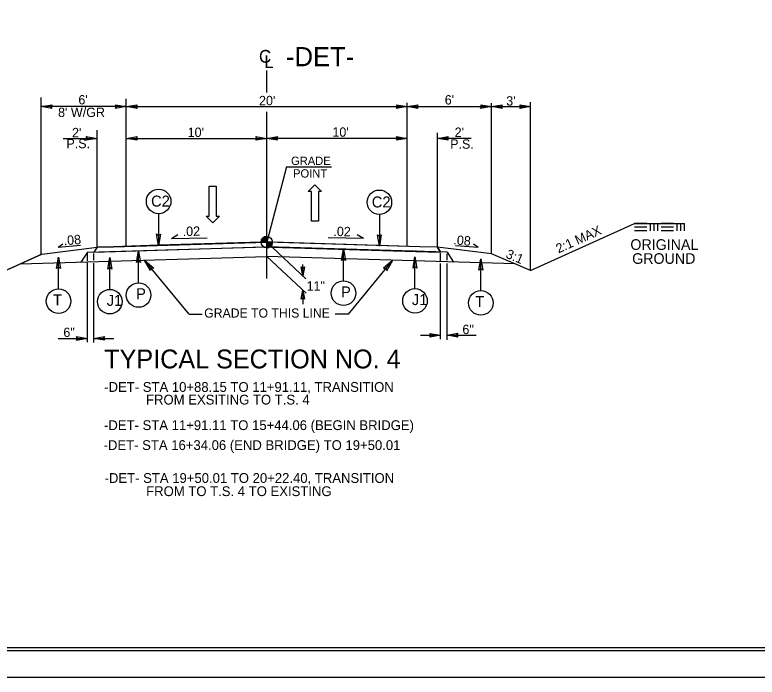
# Model space of a CAD drawing. Extents: x 9470 to 10081, y 10104 to 10463.
# Drawn here: x 9873.4 to 9960.6, y 10104 to 10181.8 of the extents above; entities that cross this region are included whole.
import ezdxf

# ---------------------------------------------------------------- set-up
doc = ezdxf.new("R2010")
doc.units = 0
for name, color, linetype in [('Default', 7, 'Continuous'), ('Old_Level_1', 7, 'Continuous'), ('Old_Level_11', 7, 'Continuous'), ('Old_Level_21', 7, 'Continuous'), ('Old_Level_28', 7, 'Continuous'), ('Old_Level_32', 7, 'Continuous'), ('Prop Dimension', 7, 'Continuous'), ('Prop Lane Arrow CELL', 7, 'Continuous'), ('Sheet Cutting Line CELL', 7, 'Continuous'), ('Sheet Plot Border Inside CELL', 7, 'Continuous'), ('Sheet Plot Border Outside CELL', 7, 'Continuous'), ('Sheet Typical CELL', 7, 'Continuous'), ('Typical Grade Point Symbol CELL', 7, 'Continuous'), ('Typical Hinge Slope Arterial CELL', 7, 'Continuous'), ('Typical ID Circle CELL', 7, 'Continuous'), ('Typical Pavement Slope CELL', 7, 'Continuous'), ('Typical Pavement Slope Information CELL', 7, 'Continuous'), ('Typical Shoulder Slope CELL', 7, 'Continuous'), ('Typical Shoulder Slope Information CELL', 7, 'Continuous'), ('Typical Slope Point Local CELL', 7, 'Continuous'), ('Typical Terminator CELL', 7, 'Continuous'), ('Typical Text General CELL', 7, 'Continuous'), ('Typical Text Grade Point CELL', 7, 'Continuous'), ('Typical Text ID Circle CELL', 7, 'Continuous'), ('Typical Text Label CELL', 7, 'Continuous')]:
    doc.layers.add(name, color=color, linetype=linetype)

msp = doc.modelspace()

# ---------------------------------------------------------------- linework, layer by layer
at = {"layer": 'Default'}
for p, q in [((9886.472, 10170.993), (9876.472, 10170.993)), ((9886.472, 10170.993), (9919.472, 10170.993)), ((9919.472, 10170.993), (9929.376, 10170.993)), ((9879.055, 10167.266), (9883.034, 10167.266)), ((9886.472, 10167.266), (9902.972, 10167.266)), ((9919.472, 10167.266), (9902.972, 10167.266)), ((9926.972, 10167.266), (9923.018, 10167.266)), ((9921.046, 10144.141), (9923.4, 10144.141)), ((9924.15, 10144.141), (9927.596, 10144.141)), ((9878.456, 10143.761), (9881.902, 10143.761)), ((9882.652, 10143.761), (9885.006, 10143.761))]:
    msp.add_line(p, q, dxfattribs=at)
at = {"layer": 'Old_Level_1'}
for p, q in [((9902.972, 10172.658), (9902.972, 10175.233)), ((9876.472, 10153.664), (9876.472, 10172.069)), ((9886.472, 10154.588), (9886.472, 10171.914)), ((9919.472, 10154.588), (9919.472, 10171.426)), ((9929.376, 10153.686), (9929.376, 10171.413)), ((9933.972, 10151.757), (9933.972, 10171.499)), ((9902.972, 10150.8), (9902.972, 10170.377)), ((9883.034, 10154.484), (9883.034, 10168.233)), ((9923.018, 10154.48), (9923.018, 10167.907)), ((9946.183, 10157.271), (9952.046, 10157.271)), ((9947.613, 10157.271), (9946.183, 10157.271)), ((9948.042, 10156.413), (9948.042, 10157.271)), ((9948.471, 10156.413), (9948.471, 10157.271)), ((9948.9, 10156.413), (9948.9, 10157.271)), ((9950.759, 10157.271), (9949.329, 10157.271)), ((9951.188, 10156.413), (9951.188, 10157.271)), ((9951.617, 10156.413), (9951.617, 10157.271)), ((9952.046, 10156.413), (9952.046, 10157.271)), ((9947.613, 10156.842), (9946.183, 10156.842)), ((9947.613, 10156.413), (9946.183, 10156.413)), ((9950.759, 10156.842), (9949.329, 10156.842)), ((9950.759, 10156.413), (9949.329, 10156.413)), ((9881.902, 10152.873), (9881.902, 10153.749)), ((9882.652, 10152.95), (9882.652, 10153.742)), ((9923.4, 10152.877), (9923.4, 10153.78)), ((9924.15, 10152.953), (9924.15, 10153.704)), ((9881.902, 10143.341), (9881.902, 10152.63)), ((9882.652, 10143.285), (9882.652, 10152.602)), ((9923.4, 10143.679), (9923.4, 10152.564)), ((9924.15, 10143.582), (9924.15, 10152.578))]:
    msp.add_line(p, q, dxfattribs=at)
at = {"layer": 'Old_Level_21'}
for p, q in [((9884.979, 10154.543), (9883.034, 10154.484)), ((9890.27, 10154.702), (9884.979, 10154.543)), ((9902.301, 10155.063), (9890.275, 10154.702)), ((9903.548, 10154.564), (9903.548, 10154.564)), ((9903.57, 10154.624), (9903.57, 10154.624)), ((9903.6, 10154.725), (9903.6, 10154.725)), ((9903.605, 10154.745), (9903.605, 10154.745)), ((9903.614, 10154.785), (9903.613, 10154.785)), ((9903.633, 10154.906), (9903.633, 10154.906)), ((9903.637, 10154.947), (9903.637, 10154.947)), ((9903.639, 10154.967), (9903.639, 10154.967)), ((9903.64, 10154.987), (9903.64, 10154.987)), ((9903.642, 10155.007), (9903.641, 10155.007)), ((9903.643, 10155.047), (9903.643, 10155.047)), ((9923.018, 10154.48), (9920.966, 10154.543)), ((9882.652, 10153.911), (9902.619, 10154.512)), ((9883.034, 10154.484), (9882.652, 10153.911)), ((9903.323, 10154.51), (9903.522, 10154.504)), ((9903.522, 10154.504), (9920.476, 10153.995)), ((9920.501, 10153.995), (9923.4, 10153.908)), ((9923.4, 10153.908), (9923.018, 10154.48))]:
    msp.add_line(p, q, dxfattribs=at)
for points in [[(9890.275, 10154.702), (9890.273, 10154.689), (9890.27, 10154.702)], [(9903.548, 10154.564), (9903.548, 10154.564)], [(9903.57, 10154.625), (9903.57, 10154.624)], [(9903.6, 10154.725), (9903.6, 10154.725)], [(9903.605, 10154.745), (9903.605, 10154.745)], [(9903.613, 10154.786), (9903.614, 10154.785)], [(9903.633, 10154.906), (9903.633, 10154.906)], [(9903.637, 10154.947), (9903.637, 10154.947)], [(9903.639, 10154.967), (9903.639, 10154.967)], [(9903.64, 10154.987), (9903.64, 10154.987)], [(9903.641, 10155.007), (9903.642, 10155.007)], [(9920.966, 10154.543), (9903.643, 10155.063), (9903.643, 10155.063)], [(9903.643, 10155.063), (9903.643, 10155.063)], [(9903.643, 10155.047), (9903.643, 10155.047)], [(9920.476, 10153.995), (9920.488, 10154.106), (9920.501, 10153.995)]]:
    msp.add_lwpolyline(points, dxfattribs=at)
for centre, radius, start, end in [((9902.972, 10155.082), 0.671, 181.65298, 238.25158), ((9902.972, 10155.082), 0.671, 301.49018, 358.34721), ((9902.255, 10155.072), 1.388, 335.85146, 359.62995)]:
    msp.add_arc(centre, radius, start, end, dxfattribs=at)
for major_axis, start_param, end_param in [((0, -1.007), 0.959512, 1.030472), ((0, 1.007), 4.172298, 4.195208), ((0, -1.007), 1.053615, 1.076478), ((0, 1.007), 4.218071, 4.240713), ((0, 1.007), 4.240976, 4.262833), ((0, -1.007), 1.12124, 1.165074), ((0, 1.007), 4.306666, 4.350076), ((0, 1.007), 4.350343, 4.371393), ((0, 1.007), 4.371407, 4.413558), ((0, 1.007), 4.413606, 4.45513), ((0, -1.007), 1.313537, 1.35457), ((0, 1.007), 4.496163, 4.537042), ((0, 1.007), 4.537042, 4.557161), ((0, -1.007), 1.415569, 1.435962), ((0, -1.007), 1.436017, 1.456131), ((0, 1.007), 4.597736, 4.617845), ((0, -1.007), 1.476273, 1.496336), ((0, 1.007), 4.637992, 4.657958), ((0, -1.007), 1.516366, 1.536422), ((0, -1.007), 1.536452, 1.551923)]:
    msp.add_ellipse((9902.972, 10155.082), major_axis=major_axis, ratio=0.666667, start_param=start_param, end_param=end_param, dxfattribs=at)
at = {"layer": 'Old_Level_28'}
for points in [[(9877.738, 10170.775), (9876.472, 10170.993), (9877.745, 10171.218), (9877.583, 10170.993)], [(9885.206, 10171.211), (9886.472, 10170.993), (9885.199, 10170.768), (9885.361, 10170.993)], [(9887.738, 10170.775), (9886.472, 10170.993), (9887.745, 10171.218), (9887.583, 10170.993)], [(9918.206, 10171.211), (9919.472, 10170.993), (9918.199, 10170.768), (9918.361, 10170.993)], [(9920.738, 10170.775), (9919.472, 10170.993), (9920.745, 10171.218), (9920.583, 10170.993)], [(9928.11, 10171.211), (9929.376, 10170.993), (9928.103, 10170.768), (9928.265, 10170.993)], [(9930.641, 10170.775), (9929.376, 10170.993), (9930.648, 10171.218), (9930.486, 10170.993)], [(9932.706, 10171.211), (9933.972, 10170.993), (9932.699, 10170.768), (9932.861, 10170.993)], [(9881.768, 10167.484), (9883.034, 10167.266), (9881.761, 10167.041), (9881.923, 10167.266)], [(9887.738, 10167.048), (9886.472, 10167.266), (9887.745, 10167.491), (9887.583, 10167.266)], [(9901.706, 10167.484), (9902.972, 10167.266), (9901.699, 10167.041), (9901.861, 10167.266)], [(9904.238, 10167.048), (9902.972, 10167.266), (9904.245, 10167.491), (9904.083, 10167.266)], [(9918.206, 10167.484), (9919.472, 10167.266), (9918.199, 10167.041), (9918.361, 10167.266)], [(9924.284, 10167.048), (9923.018, 10167.266), (9924.291, 10167.491), (9924.129, 10167.266)], [(9922.134, 10144.359), (9923.4, 10144.141), (9922.127, 10143.916), (9922.289, 10144.141)], [(9925.415, 10143.923), (9924.15, 10144.141), (9925.422, 10144.366), (9925.261, 10144.141)], [(9880.637, 10143.979), (9881.902, 10143.761), (9880.63, 10143.536), (9880.792, 10143.761)], [(9883.918, 10143.543), (9882.652, 10143.761), (9883.925, 10143.986), (9883.763, 10143.761)]]:
    msp.add_lwpolyline(points, close=True, dxfattribs=at)
at = {"layer": 'Prop Dimension'}
for p, q in [((9929.376, 10170.993), (9933.972, 10170.993)), ((9905.283, 10163.905), (9902.972, 10155.083)), ((9907.579, 10150.769), (9902.972, 10155.083)), ((9893.847, 10146.623), (9888.618, 10152.965)), ((9907.591, 10149.07), (9902.972, 10153.395)), ((9912.569, 10146.623), (9917.792, 10152.957)), ((9907.216, 10151.109), (9907.216, 10152.448)), ((9907.216, 10149.421), (9907.216, 10147.794)), ((9893.847, 10146.623), (9895.402, 10146.623)), ((9912.569, 10146.623), (9911.014, 10146.623))]:
    msp.add_line(p, q, dxfattribs=at)
at = {"layer": 'Prop Lane Arrow CELL'}
for p, q in [((9896.222, 10158.134), (9896.222, 10161.634)), ((9896.222, 10161.634), (9897.047, 10161.634)), ((9897.047, 10161.634), (9897.047, 10158.134)), ((9907.847, 10161.019), (9908.622, 10161.806)), ((9908.622, 10161.806), (9909.422, 10161.019)), ((9908.222, 10161.019), (9907.847, 10161.019)), ((9908.222, 10157.519), (9908.222, 10161.019)), ((9909.422, 10161.019), (9909.047, 10161.019)), ((9909.047, 10161.019), (9909.047, 10157.519)), ((9896.647, 10157.346), (9895.847, 10158.134)), ((9895.847, 10158.134), (9896.222, 10158.134)), ((9897.422, 10158.134), (9896.647, 10157.346)), ((9897.047, 10158.134), (9897.422, 10158.134)), ((9909.047, 10157.519), (9908.222, 10157.519))]:
    msp.add_line(p, q, dxfattribs=at)
at = {"layer": 'Sheet Cutting Line CELL'}
msp.add_line((9816.836, 10103.984), (10052.596, 10103.984), dxfattribs=at)
at = {"layer": 'Sheet Plot Border Inside CELL'}
msp.add_lwpolyline([(10051.966, 10254.841), (9818.656, 10254.841), (9818.656, 10107.127), (10051.966, 10107.127)], close=True, dxfattribs=at)
at = {"layer": 'Sheet Plot Border Outside CELL'}
msp.add_lwpolyline([(10052.596, 10257.984), (9816.836, 10257.984), (9816.836, 10103.984), (10052.596, 10103.984)], close=True, dxfattribs=at)
at = {"layer": 'Sheet Typical CELL'}
msp.add_lwpolyline([(10050.216, 10254.484), (9840.216, 10254.484), (9840.216, 10107.484), (10050.216, 10107.484)], close=True, dxfattribs=at)
at = {"layer": 'Typical Grade Point Symbol CELL'}
for p, q in [((9902.972, 10155.754), (9902.972, 10155.083)), ((9902.972, 10155.083), (9902.301, 10155.083)), ((9903.643, 10155.082), (9902.972, 10155.083)), ((9902.972, 10154.412), (9902.972, 10155.083)), ((9902.972, 10155.083), (9903.643, 10155.082))]:
    msp.add_line(p, q, dxfattribs=at)
for points in [[(9902.387, 10155.411), (9902.972, 10155.411)], [(9902.395, 10155.425), (9902.972, 10155.425)], [(9902.402, 10155.438), (9902.972, 10155.438)], [(9902.411, 10155.452), (9902.972, 10155.452)], [(9902.42, 10155.465), (9902.972, 10155.465)], [(9902.43, 10155.479), (9902.972, 10155.479)], [(9902.439, 10155.492), (9902.972, 10155.492)], [(9902.45, 10155.505), (9902.972, 10155.505)], [(9902.462, 10155.519), (9902.972, 10155.519)], [(9902.474, 10155.532), (9902.972, 10155.532)], [(9902.486, 10155.546), (9902.972, 10155.546)], [(9902.499, 10155.559), (9902.972, 10155.559)], [(9902.512, 10155.572), (9902.972, 10155.572)], [(9902.527, 10155.586), (9902.972, 10155.586)], [(9902.544, 10155.599), (9902.972, 10155.599)], [(9902.56, 10155.613), (9902.972, 10155.613)], [(9902.578, 10155.626), (9902.972, 10155.626)], [(9902.598, 10155.64), (9902.972, 10155.64)], [(9902.618, 10155.653), (9902.972, 10155.653)], [(9902.641, 10155.666), (9902.972, 10155.666)], [(9902.665, 10155.68), (9902.972, 10155.68)], [(9902.693, 10155.693), (9902.972, 10155.693)], [(9902.724, 10155.707), (9902.972, 10155.707)], [(9902.762, 10155.72), (9902.972, 10155.72)], [(9902.808, 10155.734), (9902.972, 10155.734)], [(9902.876, 10155.747), (9902.972, 10155.747)], [(9902.301, 10155.103), (9902.972, 10155.103)], [(9902.301, 10155.089), (9902.301, 10155.089), (9902.972, 10155.089)], [(9902.302, 10155.129), (9902.972, 10155.129)], [(9902.302, 10155.116), (9902.972, 10155.116)], [(9902.304, 10155.143), (9902.972, 10155.143)], [(9902.305, 10155.156), (9902.972, 10155.156)], [(9902.307, 10155.17), (9902.972, 10155.17)], [(9902.308, 10155.183), (9902.972, 10155.183)], [(9902.31, 10155.197), (9902.972, 10155.197)], [(9902.313, 10155.21), (9902.972, 10155.21)], [(9902.316, 10155.223), (9902.972, 10155.223)], [(9902.319, 10155.237), (9902.972, 10155.237)], [(9902.322, 10155.25), (9902.972, 10155.25)], [(9902.326, 10155.264), (9902.972, 10155.264)], [(9902.329, 10155.277), (9902.972, 10155.277)], [(9902.333, 10155.29), (9902.972, 10155.29)], [(9902.338, 10155.304), (9902.972, 10155.304)], [(9902.342, 10155.317), (9902.972, 10155.317)], [(9902.348, 10155.331), (9902.972, 10155.331)], [(9902.354, 10155.344), (9902.972, 10155.344)], [(9902.36, 10155.358), (9902.972, 10155.358)], [(9902.366, 10155.371), (9902.972, 10155.371)], [(9902.372, 10155.385), (9902.972, 10155.385)], [(9902.38, 10155.398), (9902.972, 10155.398)], [(9902.972, 10155.073), (9903.643, 10155.073), (9903.643, 10155.073)], [(9902.972, 10155.059), (9903.643, 10155.059)], [(9902.972, 10155.046), (9903.642, 10155.046)], [(9902.972, 10155.032), (9903.642, 10155.032)], [(9902.972, 10155.019), (9903.64, 10155.019)], [(9902.972, 10155.006), (9903.639, 10155.006)], [(9902.972, 10154.992), (9903.637, 10154.992)], [(9902.972, 10154.979), (9903.634, 10154.979)], [(9902.972, 10154.965), (9903.633, 10154.965)], [(9902.972, 10154.952), (9903.63, 10154.952)], [(9902.972, 10154.938), (9903.627, 10154.938)], [(9902.972, 10154.925), (9903.624, 10154.925)], [(9902.972, 10154.912), (9903.621, 10154.912)], [(9902.972, 10154.898), (9903.617, 10154.898)], [(9902.972, 10154.885), (9903.614, 10154.885)], [(9902.972, 10154.871), (9903.609, 10154.871)], [(9902.972, 10154.858), (9903.605, 10154.858)], [(9902.972, 10154.844), (9903.6, 10154.844)], [(9902.972, 10154.831), (9903.594, 10154.831)], [(9902.972, 10154.818), (9903.588, 10154.818)], [(9902.972, 10154.804), (9903.582, 10154.804)], [(9902.972, 10154.791), (9903.576, 10154.791)], [(9902.972, 10154.777), (9903.57, 10154.777)], [(9902.972, 10154.764), (9903.563, 10154.764)], [(9902.972, 10154.75), (9903.555, 10154.75)], [(9902.972, 10154.737), (9903.548, 10154.737)], [(9902.972, 10154.724), (9903.539, 10154.724)], [(9902.972, 10154.71), (9903.53, 10154.71)], [(9902.972, 10154.697), (9903.521, 10154.697)], [(9902.972, 10154.683), (9903.512, 10154.683)], [(9902.972, 10154.67), (9903.502, 10154.67)], [(9902.972, 10154.656), (9903.491, 10154.656)], [(9902.972, 10154.643), (9903.479, 10154.643)], [(9902.972, 10154.63), (9903.467, 10154.63)], [(9902.972, 10154.616), (9903.455, 10154.616)], [(9902.972, 10154.603), (9903.442, 10154.603)], [(9902.972, 10154.589), (9903.427, 10154.589)], [(9902.972, 10154.576), (9903.412, 10154.576)], [(9902.972, 10154.562), (9903.396, 10154.562)], [(9902.972, 10154.549), (9903.379, 10154.549)], [(9902.972, 10154.536), (9903.361, 10154.536)], [(9902.972, 10154.522), (9903.342, 10154.522)], [(9902.972, 10154.509), (9903.321, 10154.509)], [(9902.972, 10154.495), (9903.297, 10154.495)], [(9902.972, 10154.482), (9903.272, 10154.482)], [(9902.972, 10154.468), (9903.244, 10154.468)], [(9902.972, 10154.455), (9903.212, 10154.455)], [(9902.972, 10154.442), (9903.172, 10154.442)], [(9902.972, 10154.428), (9903.124, 10154.428)], [(9902.972, 10154.415), (9903.045, 10154.415)]]:
    msp.add_lwpolyline(points, dxfattribs=at)
msp.add_circle((9902.972, 10155.082), 0.671, dxfattribs=at)
for start, end in [(89.99048, 179.99048), (269.99048, 359.99048)]:
    msp.add_arc((9902.972, 10155.082), 0.671, start, end, dxfattribs=at)
at = {"layer": 'Typical Hinge Slope Arterial CELL'}
for p, q in [((9876.56, 10153.675), (9864.356, 10148.157)), ((9933.979, 10151.754), (9929.376, 10153.686))]:
    msp.add_line(p, q, dxfattribs=at)
at = {"layer": 'Typical ID Circle CELL'}
for p, q in [((9890.273, 10158.417), (9890.273, 10154.689)), ((9916.205, 10158.313), (9916.205, 10154.585)), ((9887.914, 10150.304), (9887.914, 10154.032)), ((9911.99, 10150.522), (9911.99, 10154.25)), ((9878.513, 10149.585), (9878.513, 10153.314)), ((9884.536, 10149.528), (9884.536, 10153.256)), ((9920.387, 10149.619), (9920.387, 10153.347)), ((9928.124, 10149.381), (9928.124, 10153.11))]:
    msp.add_line(p, q, dxfattribs=at)
for centre in [(9890.273, 10159.859), (9916.205, 10159.755), (9887.914, 10148.862), (9911.99, 10149.08), (9878.513, 10148.143), (9884.536, 10148.085), (9920.387, 10148.177), (9928.124, 10147.939)]:
    msp.add_circle(centre, 1.443, dxfattribs=at)
at = {"layer": 'Typical Pavement Slope CELL'}
for p, q in [((9884.979, 10154.543), (9902.972, 10155.083)), ((9920.966, 10154.543), (9902.972, 10155.083)), ((9881.902, 10153.888), (9881.137, 10152.74)), ((9881.902, 10153.888), (9902.972, 10154.52)), ((9883.034, 10154.484), (9882.652, 10153.911)), ((9924.15, 10153.885), (9902.972, 10154.52)), ((9923.018, 10154.48), (9923.4, 10153.908)), ((9924.15, 10153.885), (9924.915, 10152.737)), ((9874.021, 10152.527), (9902.972, 10153.395)), ((9932.154, 10152.52), (9902.972, 10153.395))]:
    msp.add_line(p, q, dxfattribs=at)
at = {"layer": 'Typical Pavement Slope Information CELL'}
for p, q in [((9891.764, 10155.515), (9892.512, 10155.967)), ((9891.764, 10155.515), (9895.976, 10155.599)), ((9914.327, 10155.492), (9910.18, 10155.575)), ((9914.327, 10155.492), (9913.583, 10155.942)), ((9878.45, 10154.477), (9879.006, 10154.865)), ((9878.45, 10154.477), (9881.11, 10154.705)), ((9927.823, 10154.432), (9925.164, 10154.659)), ((9927.823, 10154.432), (9927.267, 10154.819))]:
    msp.add_line(p, q, dxfattribs=at)
at = {"layer": 'Typical Shoulder Slope CELL'}
for p, q in [((9883.034, 10154.484), (9884.979, 10154.543)), ((9923.018, 10154.48), (9920.966, 10154.543)), ((9876.56, 10153.675), (9883.034, 10154.484)), ((9929.376, 10153.686), (9923.018, 10154.48))]:
    msp.add_line(p, q, dxfattribs=at)
at = {"layer": 'Typical Slope Point Local CELL'}
for p, q in [((9933.979, 10151.754), (9946.183, 10157.271)), ((9864.356, 10148.157), (9876.56, 10153.675))]:
    msp.add_line(p, q, dxfattribs=at)
at = {"layer": 'Typical Terminator CELL'}
for points in [[(9890.503, 10156.025), (9890.273, 10154.689), (9890.035, 10156.032), (9890.273, 10155.862)], [(9916.435, 10155.921), (9916.205, 10154.585), (9915.967, 10155.928), (9916.205, 10155.758)], [(9887.684, 10152.696), (9887.914, 10154.032), (9888.152, 10152.689), (9887.914, 10152.86)], [(9911.76, 10152.915), (9911.99, 10154.25), (9912.227, 10152.907), (9911.99, 10153.078)], [(9878.283, 10151.978), (9878.513, 10153.314), (9878.751, 10151.97), (9878.513, 10152.141)], [(9884.306, 10151.92), (9884.536, 10153.256), (9884.773, 10151.913), (9884.536, 10152.083)], [(9889.326, 10151.726), (9888.618, 10152.965), (9889.711, 10152.033), (9889.403, 10152.012)], [(9917.084, 10151.719), (9917.792, 10152.957), (9916.699, 10152.026), (9917.007, 10152.005)], [(9920.157, 10152.011), (9920.387, 10153.347), (9920.624, 10152.004), (9920.387, 10152.175)], [(9927.894, 10151.774), (9928.124, 10153.11), (9928.361, 10151.766), (9928.124, 10151.937)], [(9907.398, 10152.163), (9907.216, 10151.109), (9907.028, 10152.169), (9907.216, 10152.035)], [(9907.034, 10148.367), (9907.216, 10149.421), (9907.403, 10148.361), (9907.216, 10148.495)]]:
    msp.add_lwpolyline(points, close=True, dxfattribs=at)
at = {"layer": 'Typical Text Grade Point CELL'}
msp.add_line((9905.283, 10163.905), (9910.59, 10163.905), dxfattribs=at)

# ---------------------------------------------------------------- texts
at = {"layer": 'Default'}
for s, p in [("6'", (9880.846, 10171.251)), ("20'", (9902.067, 10171.152)), ("6'", (9923.884, 10171.239)), ("8' W/GR", (9878.457, 10169.771)), ("2'", (9880.098, 10167.392)), ("10'", (9893.679, 10167.431)), ("10'", (9910.684, 10167.454)), ("2'", (9925.051, 10167.435)), ('P.S.', (9879.436, 10166.105)), ('P.S.', (9924.52, 10166.045)), ('6"', (9879.078, 10143.929)), ('6"', (9925.963, 10144.279))]:
    msp.add_text(s, height=1.1, dxfattribs=at).set_placement(p)
msp.add_text('2:1 MAX', height=1.1, rotation=24.32711, dxfattribs=at).set_placement((9937.248, 10153.742))
at = {"layer": 'Old_Level_1'}
msp.add_text('C', height=1.5, dxfattribs=at).set_placement((9902.057, 10176.148))
msp.add_text('L', height=1.5, rotation=359.9469, dxfattribs=at).set_placement((9902.671, 10175.519))
at = {"layer": 'Old_Level_11'}
for s, p in [('ORIGINAL', (9945.694, 10154.165)), ('GROUND', (9945.904, 10152.525))]:
    msp.add_text(s, height=1.25, rotation=0.00126, dxfattribs=at).set_placement(p)
at = {"layer": 'Old_Level_32'}
for s, height, p in [('TYPICAL SECTION NO. 4', 2.21, (9883.884, 10140.248)), ('-DET- STA 10+88.15 TO 11+91.11, TRANSITION ', 1.15, (9883.88, 10137.488)), ('FROM EXSITING TO T.S. 4', 1.15, (9888.794, 10136.005)), ('-DET- STA 11+91.11 TO 15+44.06 (BEGIN BRIDGE)', 1.15, (9883.856, 10133.004)), ('-DET- STA 16+34.06 (END BRIDGE) TO 19+50.01', 1.15, (9883.808, 10130.663)), ('-DET- STA 19+50.01 TO 20+22.40, TRANSITION', 1.15, (9883.923, 10126.798)), ('FROM TO T.S. 4 TO EXISTING', 1.15, (9888.808, 10125.249))]:
    msp.add_text(s, height=height, dxfattribs=at).set_placement(p)
at = {"layer": 'Prop Dimension'}
msp.add_text("3'", height=1.1, dxfattribs=at).set_placement((9931.106, 10171.111))
msp.add_text('11"', height=1.1, rotation=0.00001, dxfattribs=at).set_placement((9907.657, 10149.391))
at = {"layer": 'Typical Hinge Slope Arterial CELL'}
msp.add_text('3:1', height=1.1, rotation=337.23337, dxfattribs=at).set_placement((9930.969, 10153.276))
at = {"layer": 'Typical Shoulder Slope Information CELL'}
for s, rotation, p in [('.02', 1.14574, (9893.105, 10155.787)), ('.02', 358.85426, (9910.793, 10155.798)), ('.08', 4.89013, (9879.159, 10154.697)), ('.08', 355.10987, (9924.864, 10154.816))]:
    msp.add_text(s, height=1.1, rotation=rotation, dxfattribs=at).set_placement(p)
at = {"layer": 'Typical Text General CELL'}
msp.add_text('GRADE TO THIS LINE', height=1.0742, dxfattribs=at).set_placement((9895.626, 10146.213))
at = {"layer": 'Typical Text Grade Point CELL'}
for s, p in [('GRADE', (9905.829, 10164.139)), ('POINT', (9906.065, 10162.656))]:
    msp.add_text(s, height=0.9787, dxfattribs=at).set_placement(p)
at = {"layer": 'Typical Text ID Circle CELL'}
for s, height, p in [('C2', 1.2912, (9889.382, 10159.25)), ('C2', 1.2912, (9915.314, 10159.146)), ('P', 1.291, (9887.62, 10148.367)), ('P', 1.291, (9911.695, 10148.585)), ('T ', 1.2912, (9877.863, 10147.649)), ('J1', 1.2912, (9884.173, 10147.591)), ('J1', 1.2912, (9920.024, 10147.682)), ('T ', 1.2912, (9927.474, 10147.445))]:
    msp.add_text(s, height=height, dxfattribs=at).set_placement(p)
at = {"layer": 'Typical Text Label CELL'}
msp.add_text('-DET-', height=2.25, dxfattribs=at).set_placement((9905.234, 10175.736))

doc.saveas('drawing.dxf')
